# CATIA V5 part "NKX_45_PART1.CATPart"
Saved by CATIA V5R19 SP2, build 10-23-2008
Part number: NKX_45_PART1
Bounding box of the stored display mesh (mm): x 0 to 32, y -32.393 to 32.393, z -32.491 to 32.491
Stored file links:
  G:\EU_thinkMotion\CFAO_2010\MMS_groupe2\MMS_groupe2\OK\nrosalie\nrosalie_cfao_support_d_arme_legere_final\NKX_45_PART1.CATPart
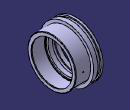
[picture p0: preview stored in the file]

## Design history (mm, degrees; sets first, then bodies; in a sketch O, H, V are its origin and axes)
Set1
  Point1: (0, 0, 0)
  Point2: (1, 0, 0)
  Point3: (0, 1, 0)
  Plane1: type 3Points, Element1 Point1, Element2 Point2, Element3 Point3
  Point4: (0, 0, 0)
  Point5: (1, 0, 0)
  Point6: (0, 0, -1)
  Plane2: type 3Points, Element1 Point4, Element2 Point5, Element3 Point6
Body1 (main body)
  Sketch1 on Plane1, origin (0, 0, 0), H (1, 0, 0), V (0, 1, 0)
    point P1 (0, 28.5)
    point P2 (0, 23.1)
    line L1 (0, 28.5) -> (0, 23.1)
    arc A1 centre (0.6, 23.1) radius 0.6 from (0, 23.1) to (0.6, 22.5) ccw
    point P3 (0.6, 22.5)
    point P4 (5.214, 22.5)
    line L2 (0.6, 22.5) -> (5.214, 22.5)
    point P5 (5.214, 22.5)
    point P6 (5.214, 23.928)
    line L3 (5.214, 22.5) -> (5.214, 23.928)
    point P7 (5.214, 23.928)
    point P8 (8.786, 23.928)
    line L4 (5.214, 23.928) -> (8.786, 23.928)
    point P9 (8.786, 23.928)
    point P10 (8.786, 22.5)
    line L5 (8.786, 23.928) -> (8.786, 22.5)
    point P11 (8.786, 22.5)
    point P12 (14, 22.5)
    line L6 (8.786, 22.5) -> (14, 22.5)
    point P13 (14, 22.5)
    point P14 (14, 24.75)
    line L7 (14, 22.5) -> (14, 24.75)
    point P15 (14, 24.75)
    point P16 (15.1, 24.75)
    line L8 (14, 24.75) -> (15.1, 24.75)
    point P17 (15.1, 24.75)
    point P18 (15.1, 25.5)
    line L9 (15.1, 24.75) -> (15.1, 25.5)
    point P19 (15.1, 25.5)
    point P20 (30.9, 25.5)
    line L10 (15.1, 25.5) -> (30.9, 25.5)
    point P21 (30.9, 25.5)
    point P22 (30.9, 24.75)
    line L11 (30.9, 25.5) -> (30.9, 24.75)
    point P23 (30.9, 24.75)
    point P24 (32, 24.75)
    line L12 (30.9, 24.75) -> (32, 24.75)
    point P25 (32, 24.75)
    point P26 (32, 28.4)
    line L13 (32, 24.75) -> (32, 28.4)
    arc A2 centre (31.4, 28.4) radius 0.6 from (32, 28.4) to (31.4, 29) ccw
    point P27 (31.4, 29)
    point P28 (14, 29)
    line L14 (31.4, 29) -> (14, 29)
    point P29 (14, 29)
    point P30 (14, 32.5)
    line L15 (14, 29) -> (14, 32.5)
    point P31 (14, 32.5)
    point P32 (8.786, 32.5)
    line L16 (14, 32.5) -> (8.786, 32.5)
    point P33 (8.786, 32.5)
    point P34 (8.786, 31.072)
    line L17 (8.786, 32.5) -> (8.786, 31.072)
    point P35 (8.786, 31.072)
    point P36 (5.214, 31.072)
    line L18 (8.786, 31.072) -> (5.214, 31.072)
    point P37 (5.214, 31.072)
    point P38 (5.214, 32.5)
    line L19 (5.214, 31.072) -> (5.214, 32.5)
    point P39 (5.214, 32.5)
    point P40 (2.607, 32.5)
    line L20 (5.214, 32.5) -> (2.607, 32.5)
    point P41 (2.607, 32.5)
    point P42 (2.607, 28.5)
    line L21 (2.607, 32.5) -> (2.607, 28.5)
    point P43 (2.607, 28.5)
    point P44 (0, 28.5)
    line L22 (2.607, 28.5) -> (0, 28.5)
    point P45 (50, 0)
    point P46 (-50, 0)
    axis line L23 (50, 0) -> (-50, 0)
    point P47 (0, 28.5)
    point P48 (0, 23.1)
    point P49 (0, 23.1)
    point P50 (0.6, 22.5)
    point P51 (0.6, 22.5)
    point P52 (5.214, 22.5)
    point P53 (5.214, 22.5)
    point P54 (5.214, 23.928)
    point P55 (5.214, 23.928)
    point P56 (8.786, 23.928)
    point P57 (8.786, 23.928)
    point P58 (8.786, 22.5)
    point P59 (8.786, 22.5)
    point P60 (14, 22.5)
    point P61 (14, 22.5)
    point P62 (14, 24.75)
    point P63 (14, 24.75)
    point P64 (15.1, 24.75)
    point P65 (15.1, 24.75)
    point P66 (15.1, 25.5)
    point P67 (15.1, 25.5)
    point P68 (30.9, 25.5)
    point P69 (30.9, 25.5)
    point P70 (30.9, 24.75)
    point P71 (30.9, 24.75)
    point P72 (32, 24.75)
    point P73 (32, 24.75)
    point P74 (32, 28.4)
    point P75 (32, 28.4)
    point P76 (31.4, 29)
    point P77 (31.4, 29)
    point P78 (14, 29)
    point P79 (14, 29)
    point P80 (14, 32.5)
    point P81 (14, 32.5)
    point P82 (8.786, 32.5)
    point P83 (8.786, 32.5)
    point P84 (8.786, 31.072)
    point P85 (8.786, 31.072)
    point P86 (5.214, 31.072)
    point P87 (5.214, 31.072)
    point P88 (5.214, 32.5)
    point P89 (5.214, 32.5)
    point P90 (2.607, 32.5)
    point P91 (2.607, 32.5)
    point P92 (2.607, 28.5)
    point P93 (2.607, 28.5)
    point P94 (0, 28.5)
    coincidence: P47 P94, P48 P49, P50 P51, P52 P53, P54 P55, P56 P57, P58 P59, P60 P61, P62 P63, P64 P65, P66 P67, P68 P69, P70 P71, P72 P73, P74 P75, P76 P77, P78 P79, P80 P81, P82 P83, P84 P85, P86 P87, P88 P89, P90 P91, P92 P93
  Shaft1: profile Sketch1, axis Sketch1.L23, angle 0, second angle 360
  Sketch2 on Plane2, origin (0, 0, 0), H (1, 0, 0), V (0, 0, -1)
    point P1 (23, 0)
    circle A1 centre (23, 0) radius 0.79
  Pocket1: profile Sketch2, direction (0, 1, 0), length 31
